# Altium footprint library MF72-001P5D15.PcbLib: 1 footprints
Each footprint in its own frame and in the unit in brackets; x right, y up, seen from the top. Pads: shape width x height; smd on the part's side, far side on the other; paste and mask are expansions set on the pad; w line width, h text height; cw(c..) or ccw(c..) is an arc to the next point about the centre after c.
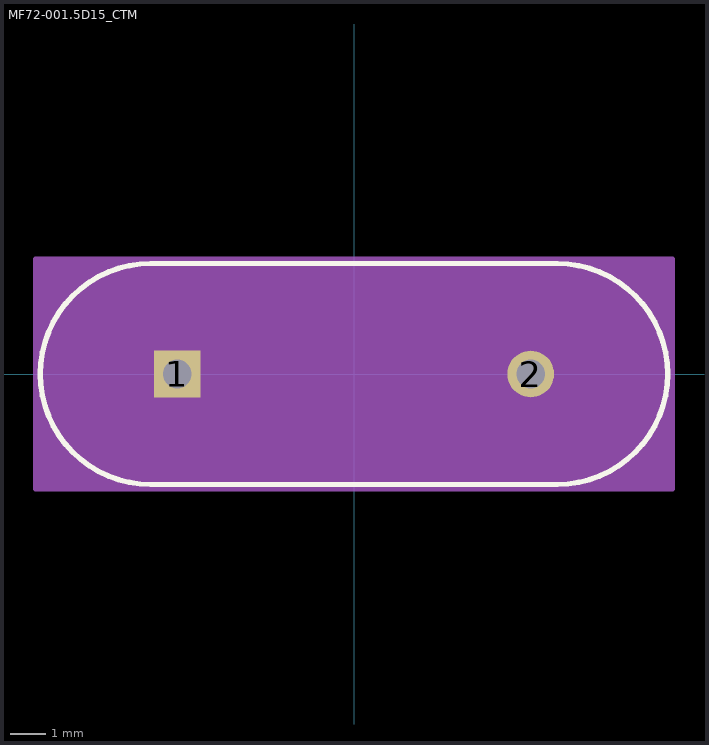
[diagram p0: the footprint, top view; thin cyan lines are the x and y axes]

## MF72-001.5D15_CTM [mil]
pads (2):
  rect 52x52 hole 32 paste-26 mask+0: 1(-196.85,0)
  round 52 hole 32 paste-26 mask+0: 2(196.85,0)
Top Overlay:
  lines w6: -226.38,-123.11 226.38,-123.11 ccw(c226.38,0) 349.49,0 ccw(c226.38,0) 226.38,123.11 -226.38,123.11 ccw(c-226.38,0) -226.38,-123.11
  text ".Designator" at -137.5,-25 h50
Mechanical 13:
  lines w1: -226.38,-118.11 226.38,-118.11 ccw(c226.38,0) 226.38,118.11 -226.38,118.11 ccw(c-226.38,0) -226.38,-118.11
  text ".Designator" at -137.5,-25 h50
Mechanical 15:
  region: 354.49,-128.11 -354.49,-128.11 -354.49,128.11 354.49,128.11
  lines w6: -354.49,-128.11 -354.49,128.11 354.49,128.11 354.49,-128.11 -354.49,-128.11
3D body "MF72-0015D15_CTM.step": height 846.46, standoff -159.09, extent -147.64,-118.11 541.34,118.11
